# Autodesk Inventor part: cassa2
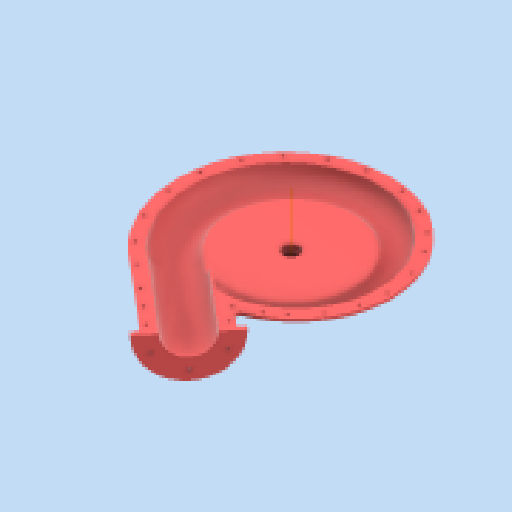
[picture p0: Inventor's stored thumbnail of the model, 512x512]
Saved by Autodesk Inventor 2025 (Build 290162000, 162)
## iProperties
Created: 2025-04
Part Number: cassa2
Material: Plastica ABS
Document SubType Name: Modeling
Designer: R5800u
Density: 1.06 g/cm^3
Appearance: Liscia - Rosso
Author: R5800u
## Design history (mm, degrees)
sketch "Schizzo31"
  geometry: C1 r 81 at (0, 0); 1 further point
  constraints: 1 centre point, 1 coincident
  dimensions: "d130" = 162 diameter of C1
feature "SupEstrusione1" sketch "Schizzo31" dims "d131" = 20, "d132" = 0
sketch "Schizzo32"
  geometry: L1 (20, -81)-(20, 81) reference; L2 (0, 81)-(20, 81) reference; L3 (0, -81)-(0, 81) reference; L4 (0, -81)-(20, -81) reference; L5 (10, 81)-(10, 91); L6 (22, 83.517)-(22, 76.086); L7 (-2, 83.517)-(-2, 76.086); L8 (0, 0)-(60.308, 0) reference; L9 (0, -81)-(20, -81); L10 (10, -81)-(10, -99); L11 (22, -76.397)-(22, -82.267); L12 (-2, -76.397)-(-2, -82.267); A1 r 14.142 centre (10, 91) between (22, 83.517) and (-2, 83.517); A2 r 19.142 centre (10, 91) between (22, 76.086) and (-2, 76.086); A3 r 20.591 centre (10, -99) between (-2, -82.267) and (22, -82.267); A4 r 25.591 centre (10, -99) between (-2, -76.397) and (22, -76.397)
  constraints: 19 end point, 8 point on circle, 5 vertical, 4 centre point, 2 coincident, 2 horizontal, 2 midpoint, 1 parallel, 1 symmetric about line
  dimensions: "d133" = 10 distance of L5.start L5.end; "d134" = 5 radial gap between concentric circles of A1 A2; "d135" = 2 distance between parallel lines of L1 L6; "d136" = 2 distance between parallel lines of L7 L3; "d137" = 14.14214 radius of A1; "d138" = 18 distance of L10.start L10.end; "d139" = 5 radial gap between concentric circles of A3 A4; "d140" = 2 distance between parallel lines of L12 L3; "d141" = 2 distance between parallel lines of L1 L11
sketch "Schizzo33"
  geometry: L1 (81, 20)-(-81, 20) reference; L2 (81, 0)-(81, 20) reference; L3 (81, 0)-(-81, 0) reference; L4 (-81, 0)-(-81, 20) reference; L5 (81, 10)-(95, 10); L6 (-81, 10)-(-103, 10); L7 (82.671, 22)-(76.317, 22); L8 (82.671, -2)-(76.317, -2); L9 (-76.417, 22)-(-82.024, 22); L10 (-76.417, -2)-(-82.024, -2); A1 r 17.205 centre (95, 10) between (82.671, -2) and (82.671, 22); A2 r 24.166 centre (-103, 10) between (-82.024, 22) and (-82.024, -2); A3 r 22.205 centre (95, 10) between (76.317, -2) and (76.317, 22); A4 r 29.166 centre (-103, 10) between (-76.417, 22) and (-76.417, -2); 1 further point
  constraints: 14 end point, 9 point on circle, 4 centre point, 4 point on line, 2 coincident, 2 horizontal, 2 midpoint, 1 parallel, 1 perpendicular
  dimensions: "d142" = 14 distance of L5.start L5.end; "d143" = 22 distance of L6.start L6.end; "d144" = 5 radial gap between concentric circles of A1 A3; "d145" = 5 radial gap between concentric circles of A2 A4; "d146" = 2 distance between parallel lines of L1 L9; "d147" = 2 distance between parallel lines of L10 L3; "d148" = 2 distance between parallel lines of L1 L7 (derived); "d149" = 2 distance between parallel lines of L8 L3 (derived)
node "Piano di lavoro32"
sketch "Schizzo34"
  geometry: L1 (20, -81)-(20, 81) reference; L2 (0, -81)-(0, 81) reference; L3 (0, 81)-(20, 81) reference; L4 (0, -81)-(20, -81) reference; L5 (10, -81)-(10, -107); L6 (22, -76.413)-(22, -81.86); L7 (-2, -81.86)-(-2, -76.413); A1 r 27.857 centre (10, -107) between (-2, -81.86) and (22, -81.86); A2 r 32.857 centre (10, -107) between (-2, -76.413) and (22, -76.413); 1 further point
  constraints: 7 end point, 4 point on circle, 2 centre point, 2 vertical, 1 coincident, 1 midpoint
  dimensions: "d151" = 26 distance of L5.start L5.end; "d152" = 5 radial gap between concentric circles of A1 A2; "d153" = 2 distance between parallel lines of L1 L6; "d154" = 2 distance between parallel lines of L2 L7
node "Piano di lavoro33"
sketch "Schizzo35"
  geometry: L1 (41.82, -0.078)-(-48.135, -0.078); L2 (103, 99)-(103, 34.826); L3 (-95, 99)-(-95.112, 30.351); A1 r 91.227 centre (-3.773, 98.851) between (0, 190) and (-95, 99); A2 r 98.916 centre (3.916, 98.839) between (-95, 99) and (0, 0); A3 r 99.078 centre (3.922, 99) between (0, 0) and (103, 99); A4 r 115.273 centre (-12.273, 99) between (103, 99) and (68.778, 180.967); 1 further point
  constraints: 8 point on circle, 6 end point, 6 tangent, 4 centre point, 1 horizontal, 1 vertical
sketch "Schizzo36"
  geometry: L1 (22, -76.397)-(22, -82.267) reference; L2 (-2, -76.397)-(-2, -82.267) reference; L3 (23, -76.957)-(23, -83.031); L4 (-3, -76.957)-(-3, -83.031); A1 r 25.591 centre (10, -99) between (-2, -76.397) and (22, -76.397) reference; A2 r 20.591 centre (10, -99) between (-2, -82.267) and (22, -82.267) reference; 1 further point
  constraints: 4 end point, 4 point on circle, 1 parallel, 1 vertical
  dimensions: "d201" = 1 distance between parallel lines of L1 L3; "d202" = 1 distance between parallel lines of L2 L4
sketch "Schizzo37"
  geometry: L1 (-76.417, 22)-(-82.024, 22) reference; L2 (-76.417, -2)-(-82.024, -2) reference; L3 (-82.628, 23)-(-76.891, 23); L4 (-82.628, -3)-(-76.891, -3); A1 r 29.166 centre (-103, 10) between (-76.417, 22) and (-76.417, -2) reference; A2 r 24.166 centre (-103, 10) between (-82.024, 22) and (-82.024, -2) reference; 1 further point
  constraints: 4 end point, 4 point on circle, 2 horizontal
  dimensions: "d199" = 1 distance between parallel lines of L1 L3; "d200" = 1 distance between parallel lines of L4 L2
loft "Loft7" sketch "Schizzo35", "Schizzo36", "Schizzo37" dims "d155" = 0, "d156" = 90 deg, "d157" = 0, "d158" = 90 deg, "d159" = 0, "d160" = 90 deg, "d161" = 0, "d162" = 90 deg, "d163" = 0, "d164" = 90 deg, "d165" = 0, "d166" = 90 deg
sketch "Schizzo38"
  geometry: L1 (25.14, 12)-(30.587, 12) reference; L2 (30.587, -12)-(25.14, -12) reference; A1 r 32.857 centre (0, 0) between (30.587, 12) and (30.587, -12) reference; A2 r 27.857 centre (0, 0) between (25.14, 12) and (25.14, -12) reference; 1 further point
sketch "Schizzo39"
  geometry: L1 (-14.914, -12)-(-7.483, -12) reference; L2 (-7.483, 12)-(-14.914, 12) reference; A1 r 19.142 centre (0, 0) between (-14.914, -12) and (-14.914, 12) reference; A2 r 19.142 centre (0, 0) between (-14.914, -12) and (-14.914, 12) reference; A3 r 14.142 centre (0, 0) between (-7.483, -12) and (-7.483, 12) reference; 1 further point
  node "Linea chiusa proiettata3"
sketch "Schizzo40"
  geometry: L1 (0, 182.517)-(0, 204.142) reference; L2 (52.619, 161.709)-(86.684, 202.306) reference; L3 (89.898, 206.137)-(49.117, 157.536) reference; A1 r 68.972 centre (25.317, 129.172) between (69.652, 182.007) and (0, 193.329); A2 r 65.893 centre (4.197, 109.327) between (49.117, 157.536) and (0, 175.086); 1 further point
  constraints: 4 point on circle, 2 centre point, 2 midpoint, 1 line through centre, 2 other
loft "Loft9" sketch "Schizzo40" dims "d173" = 0, "d174" = 90 deg, "d175" = 0, "d176" = 90 deg, "d177" = 0, "d178" = 90 deg
  node "Spigoli6"
  node "Spigoli7"
sketch "Schizzo41"
  geometry: L1 (22, -81.86)-(22, -76.413) reference; L2 (-2, -76.413)-(-2, -81.86) reference; A1 r 32.857 centre (10, -107) between (-2, -76.413) and (22, -76.413) reference; A2 r 27.857 centre (10, -107) between (-2, -81.86) and (22, -81.86) reference; 1 further point
extrude "Estrusione4" join sketch "Schizzo41" distance "d179" = 133.25; taper "d180" = 0 deg
sketch "Schizzo42"
  geometry: L1 (5.008, -4.994)-(64.281, -4.994) reference; L2 (64.281, 0.453)-(64.281, -4.994) reference; L3 (-1.203, 0.453)-(64.281, 0.453) reference; L4 (-57.207, 0.453)-(-8.066, 0.453) reference; L5 (-35.072, -4.994)-(-5.98, -4.994) reference; 2 further points
  constraints: 4 other
extrude "Estrusione5" join sketch "Schizzo42" stored distance "d181" = 133.25; taper "d182" = 0 deg
sketch "Schizzo43"
  geometry: L1 (-76.413, 22)-(-76.413, -2) reference; L2 (-81.86, 22)-(-81.86, -2) reference; A1 r 32.857 centre (-107, 10) between (-76.413, 22) and (-76.413, -2) reference; A2 r 27.857 centre (-107, 10) between (-81.86, 22) and (-81.86, -2) reference; 1 further point
extrude "Estrusione6" cut sketch "Schizzo43" stored distance "d183" = 131.5; taper "d184" = 0 deg
sketch "Schizzo45"
  geometry: L1 (0, 0)-(29.092, 0) reference; L2 (-22.135, -5.447)-(27.006, -5.447) reference; L3 (-33.897, 0)-(-27.051, 0) reference; 1 further point
  constraints: 1 horizontal alignment, 2 other
extrude "Estrusione7" join sketch "Schizzo45" distance "d185" = 23; taper "d186" = 0 deg
sketch "Schizzo46"
  geometry: L1 (-81.86, 22)-(-81.86, -2) reference; A1 r 27.857 centre (-107, 10) between (-81.86, 22) and (-81.86, -2) reference; 3 further points
  constraints: 1 coincident, 3 other
extrude "Estrusione8" cut sketch "Schizzo46" stored distance "d187" = 23; taper "d188" = 0 deg
sketch "Schizzo47"
  geometry: L1 (-76.039, -1)-(-76.039, 21.602) reference; L2 (-76.413, 22)-(-76.413, -2) reference; L3 (-76.413, 22)-(-76.413, -2) reference; C1 r 27.857 at (-107, 10); C2 r 27.857 at (-107, 10) reference; C3 r 27.857 at (-107, 10) reference; A1 r 27.857 centre (-107, 10) between (-92.729, 33.924) and (-92.729, -13.924) reference; A2 r 32.857 centre (-107, 10) between (-76.413, 22) and (-76.413, -2) reference; A3 r 32.857 centre (-107, 10) between (-76.413, 22) and (-76.413, -2) reference; 4 further points
  constraints: 2 coincident, 1 centre point, 3 other
extrude "Estrusione9" join sketch "Schizzo47" distance "d189" = 100; taper "d190" = 0 deg
node "Asse di lavoro2"
sketch "Schizzo48"
  geometry: C1 r 82 at (0, 0); 1 further point
  constraints: 1 centre point, 1 coincident
  dimensions: "d193" = 164 diameter of C1
extrude "Estrusione10" cut sketch "Schizzo48" extent not by distance; stored distance "d194" = 0; taper "d195" = 0 deg
sketch "Schizzo50"
  geometry: A1 r 27.857 centre (-107, 10) between (-92.729, 33.924) and (-92.729, -13.924) reference; A2 r 32.857 centre (-107, 10) between (-76.413, 22) and (-90.361, 38.332) reference; 7 further points
  constraints: 2 coincident, 5 other
extrude "Estrusione12" join sketch "Schizzo50" distance "d203" = 61.389; taper "d204" = 0 deg
sketch "Schizzo51"
  geometry: C1 r 198.377 at (0, 99); 1 further point
  constraints: 1 centre point, 1 coincident
extrude "Estrusione13" cut sketch "Schizzo51" extent not by distance; stored distance "d205" = 0; taper "d206" = 0 deg
fillet "Raccordo7" dims "d225" = 2
sketch "Schizzo57"
  geometry: L1 (0, 0)-(-52.681, 0); L2 (10, -119.591)-(10, -124.591) reference; L3 (-9.129, -82)-(-2, -82) reference; L4 (10, 182.57)-(10, 176.043) reference; L5 (10, 103.314)-(10, 99.75) reference; L6 (10, 99.75)-(-1.11, 99.75) reference; L7 (-2, 82)-(-6.894, 82) reference; L8 (-2, -82.267)-(-2, 0); L9 (-71.789, 0)-(61.964, 0) reference; L10 (-9.129, -82)-(-9.129, 0); 7 further points; 2 other entities
  constraints: 6 end point, 2 perpendicular, 2 point on line, 2 vertical alignment, 1 horizontal, 7 other
revolve "Rivoluzione3" sketch "Schizzo57" stored, may be unused: angle "d236" = 90 deg
fillet "Raccordo8" dims "d237" = 3
sketch "Schizzo58"
  geometry: C1 r 21 at (0, 0); 1 further point
  constraints: 1 centre point, 1 coincident
  dimensions: "d238" = 42 diameter of C1
extrude "Estrusione16" cut sketch "Schizzo58" distance "d239" = 12.5; taper "d240" = 0 deg
sketch "Schizzo59"
  geometry: L1 (-25.401, -181)-(-23.646, -178.908) reference; L2 (51.203, -245.279)-(-25.401, -181) reference; L3 (54.417, -241.448)-(51.203, -245.279) reference; L4 (15.563, -208.846)-(54.417, -241.448) reference; L5 (12.177, -291.788)-(-89.898, -206.137) reference; L6 (15.391, -287.958)-(12.177, -291.788) reference; L7 (-86.684, -202.306)-(15.391, -287.958) reference; L8 (7.39, -201.988)-(10.033, -204.205) reference; L9 (5.931, -203.727)-(7.39, -201.988) reference; L10 (-23.646, -178.908)-(5.931, -203.727) reference; L11 (42.366, -215.671)-(71.323, -239.969); L12 (71.323, -239.969)-(52.682, -262.185); L13 (52.682, -262.185)-(-42.307, -182.479); L14 (-42.307, -182.479)-(-25.125, -162.002); L15 (-25.125, -162.002)-(4.452, -186.821); L16 (4.452, -186.821)-(5.911, -185.082); L17 (5.911, -185.082)-(14.059, -191.919); L18 (-78.513, -193.498)-(32.297, -286.479); L19 (32.297, -286.479)-(13.656, -308.694); L20 (13.656, -308.694)-(-98.044, -214.966); L21 (12.177, -291.788)-(11.546, -292.54); L22 (11.546, -292.54)-(4.464, -300.98); L23 (54.417, -241.448)-(62.131, -232.256); 1 further point
  constraints: 26 end point, 3 parallel, 3 point on line, 1 perpendicular, 16 other
  dimensions: "d241" = 12 distance between parallel lines of L5 L20
extrude "Estrusione17" join sketch "Schizzo59" distance "d242" = 5; taper "d243" = 0 deg
fillet "Raccordo9" dims "d244" = 5
fillet "Raccordo10" dims "d245" = 2
sketch "Schizzo60"
  geometry: C1 r 21 at (0, 0) reference; C2 r 35 at (0, 0); 1 further point
  constraints: 1 centre point, 1 coincident
  dimensions: "d246" = 70 diameter of C2
extrude "Estrusione18" join sketch "Schizzo60" distance "d247" = 45; taper "d248" = 0 deg
sketch "Schizzo61"
  geometry: C1 r 10.5 at (0, 0); C2 r 21 at (0, 0) reference; 1 further point
  constraints: 1 centre point, 1 coincident
  dimensions: "d249" = 21 diameter of C1
extrude "Estrusione19" join sketch "Schizzo61" distance "d250" = 5; taper "d251" = 0 deg
sketch "Schizzo62"
  geometry: L1 (-21, -38.954)-(-21, -6.825) reference; L2 (0, -43.526)-(0, 57.254) reference; L3 (-12.5, -7)-(-12.5, -9.5); L4 (-12.5, -9.5)-(-10.5, -11.5); L5 (-12.5, -9.5)-(-9.672, -9.5); L6 (-10.5, -7)-(-10.5, -2) reference; L7 (-10.5, -23)-(-16.5, -28); L8 (-16.5, -28)-(-21, -28); L9 (-10.5, -13.5)-(-12.5, -13.5); L10 (-12.5, -13.5)-(-12.5, -16); L11 (-12.5, -16)-(-10.5, -18); L12 (-10.5, -11.5)-(-10.5, -13.5); L13 (-10.5, -18)-(-10.5, -23); L14 (-12.5, -9.5)-(-10.5, -11.5); 5 further points; 2 other entities
  constraints: 24 end point, 3 vertical, 2 horizontal, 2 perpendicular, 2 point on line, 1 collinear, 1 equal length, 8 other
  dimensions: "d258" = 45 deg angle of L4 L5; "d259" = 2.5 distance of L3.start L3.end; "d261" = 5 distance from line of L7.start L8; "d266" = 2.5 distance of L9.end L10.end; "d267" = 2 distance from line of L4.end L9; "d269" = 135 deg angle of L10 L11; "d270" = 8.5 distance between parallel lines of L1 L3; "d271" = 2 horizontal distance of L4.end L3.end; "d272" = 2 horizontal distance of L11.end L10.end; "d273" = 5 distance of L11.end L7.start; "d274" = 4.5 distance of L7.end L8.end
revolve "Rivoluzione4" sketch "Schizzo62" stored, may be unused: angle "d254" = 360 deg
fillet "Raccordo11" dims "d256" = 10
fillet "Raccordo12" dims "d263" = 12
fillet "Raccordo13" dims "d264" = 2
fillet "Raccordo14" dims "d265" = 3
sketch "Schizzo63"
  geometry: L1 (-76.682, 10)-(-79.143, 10) reference; L2 (-107, 10)-(-52, 10); L3 (-62.143, 10)-(-62.143, 7) reference; L4 (-107, 10)-(-162, 10); C1 r 32.857 at (-107, 10); A1 r 32.857 centre (-107, 10) between (-139.474, 5) and (-74.526, 5) reference; A2 r 55 centre (-107, 10) between (-52, 10) and (-162, 10); 4 further points
  constraints: 4 end point, 3 coincident, 2 centre point, 2 point on circle, 1 concentric, 1 perpendicular, 1 point on line, 3 other
  dimensions: "d275" = 110 diameter of A2
extrude "Estrusione20" join sketch "Schizzo63" distance "d276" = 6; taper "d277" = 0 deg
fillet "Raccordo15" dims "d278" = 2
sketch "Schizzo64"
  geometry: L1 (-52, 10)-(-79.143, 10) reference; L2 (-134.857, 10)-(-162, 10) reference; L3 (-134.857, 10)-(115.644, 10) reference; A1 r 27.857 centre (-107, 10) between (-134.857, 10) and (-79.143, 10) reference; A2 r 55 centre (-107, 10) between (-162, 10) and (-52, 10) reference; A3 r 27.857 centre (-107, 10) between (-134.857, 10) and (-79.143, 10) reference; 2 further points
  dimensions: "d279" = 42 distance of point (-107, -32) A1.centre
hole "Foro1" sketch "Schizzo64" at (-107, -32) diameter "d280" = 4.917; stored, may be unused: countersink angle "d284" = 90 deg, drill point angle "d286" = 118 deg; dims "d281" = 12, "d282" = 4, "d283" = 2, "d285" = 17.1
pattern_circular "Serie circolare1" dims angle "d288" = 360 deg
sketch "Schizzo65"
  geometry: L1 (10.891, 290.209)-(4.217, 298.163) reference; L2 (-89.652, 205.843)-(10.891, 290.209) reference; L3 (52.639, 240.456)-(14.31, 208.294) reference; L4 (59.313, 232.502)-(52.639, 240.456) reference; L5 (47.792, 222.836)-(59.313, 232.502) reference; L6 (4.217, 298.163)-(-96.686, 213.495) reference; C1 r 2.15 at (37.319, 213.031) reference; C2 r 2.15 at (-20.957, 271.318) reference; C3 r 2.15 at (1.557, 290.209) reference; C4 r 2.15 at (-43.346, 252.531) reference; C5 r 2.15 at (-72.504, 228.065) reference; C6 r 2.15 at (-100.633, 202.792) reference; C7 r 2.15 at (-123.271, 167.812) reference; C8 r 2.15 at (-136.274, 123.671) reference; C9 r 2.15 at (-136.274, 81.939) reference; C10 r 2.15 at (-123.271, 41.199) reference; C11 r 2.15 at (-100.633, 9.223) reference; C12 r 2.15 at (-67.284, -16.016) reference; C13 r 2.15 at (-29.582, -29.099) reference; C14 r 2.15 at (17.48, -29.099) reference; C15 r 2.15 at (51.045, -17.961) reference; C16 r 2.15 at (80.785, 2.282) reference; C17 r 2.15 at (100.772, 25.36) reference; C18 r 2.15 at (116.54, 57.793) reference; C19 r 2.15 at (122.655, 96.252) reference; C20 r 2.15 at (118.476, 128.067) reference; C21 r 2.15 at (104.465, 159.922) reference; C22 r 2.15 at (82.518, 185.658) reference; C23 r 2.15 at (63.257, 199.379) reference; C24 r 2.15 at (51.045, 231.286) reference; 3 further points
hole "Foro2" sketch "Schizzo65" diameter "d290" = 4.3; stored, may be unused: countersink angle "d294" = 90 deg, drill point angle "d296" = 118 deg; dims "d291" = 6, "d292" = 8, "d293" = 4.6, "d295" = 8
node "Solido7"
node "Superf1"
node "Linea chiusa proiettata4"
node "Linea chiusa proiettata5"
node "Linea chiusa proiettata6"
node "Linea chiusa proiettata7"
node "Linea chiusa proiettata8"
node "Linea chiusa proiettata11"
node "Linea chiusa proiettata13"
node "Riferimento4"
node "Riferimento5"
node "Proietta spigoli di taglio2"
other parameters: "d150" = 140 deg
